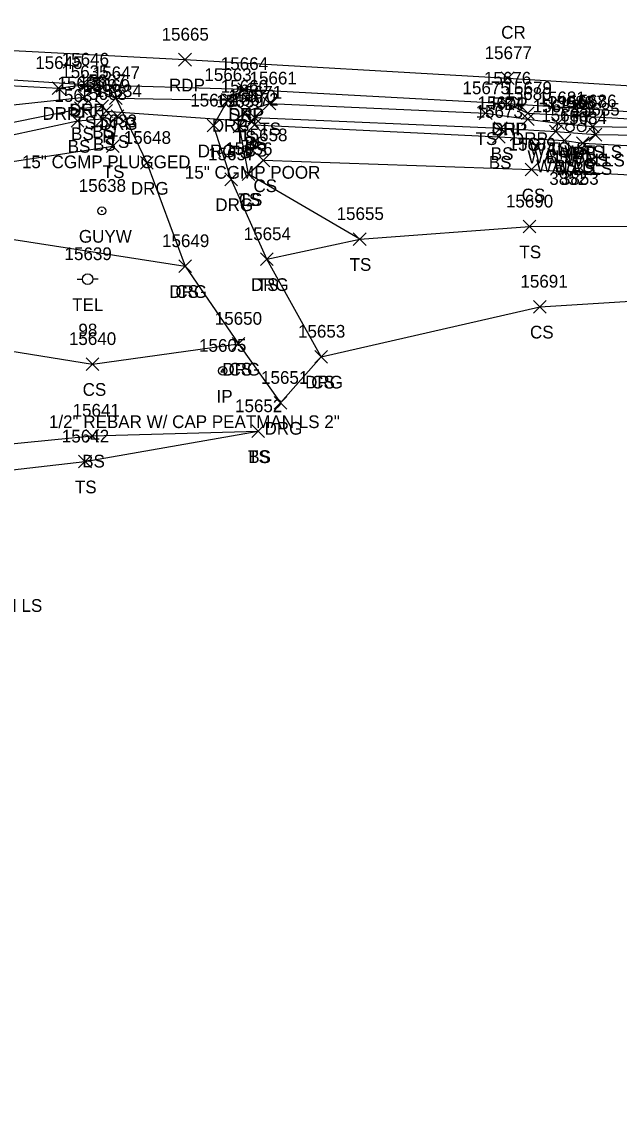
# Model space of a CAD drawing. Extents: x 1606530 to 1613020, y 784959 to 789666.
# Drawn here: x 1609492.8 to 1609586.7, y 788263.1 to 788433.6 of the extents above; entities that cross this region are included whole.
import ezdxf

# ---------------------------------------------------------------- set-up
doc = ezdxf.new("R2010")
doc.units = 0
for name, color, linetype in [('D_A', 7, 'Continuous'), ('D_C', 7, 'Continuous'), ('D_I', 7, 'Continuous'), ('D_TIC', 7, 'Continuous'), ('DCP', 7, 'Continuous'), ('L_A', 7, 'Continuous'), ('L_C', 7, 'Continuous'), ('L_I', 7, 'Continuous'), ('L_TIC', 7, 'Continuous'), ('LELB', 7, 'Continuous'), ('LMB', 7, 'Continuous'), ('LWS', 7, 'Continuous'), ('M_A', 7, 'Continuous'), ('M_C', 7, 'Continuous'), ('M_I', 7, 'Continuous'), ('MPIR', 7, 'Continuous'), ('P_A', 7, 'Continuous'), ('P_I', 7, 'Continuous'), ('P_TIC', 7, 'Continuous'), ('PET', 7, 'Continuous'), ('PSP', 7, 'Continuous'), ('R_A', 7, 'Continuous'), ('R_I', 7, 'Continuous'), ('R_TIC', 7, 'Continuous'), ('RDG', 7, 'Continuous'), ('RDP', 7, 'Continuous'), ('U_A', 7, 'Continuous'), ('U_C', 7, 'Continuous'), ('U_I', 7, 'Continuous'), ('UP', 7, 'Continuous'), ('UPGW', 7, 'Continuous')]:
    doc.layers.add(name, color=color, linetype=linetype)

msp = doc.modelspace()

# ---------------------------------------------------------------- linework, layer by layer
at = {"layer": 'D_TIC'}
for points in [[(1609505.07, 788418.52), (1609507.07, 788420.52)], [(1609507.07, 788418.52), (1609505.07, 788420.52)], [(1609528, 788416.87), (1609530, 788418.87)], [(1609530, 788416.87), (1609528, 788418.87)]]:
    msp.add_lwpolyline(points, dxfattribs=at)
at = {"layer": 'DCP'}
msp.add_lwpolyline([(1609506.07, 788419.52), (1609529, 788417.87)], dxfattribs=at)
at = {"layer": 'L_TIC'}
for points in [[(1609501.63, 788420.7), (1609503.63, 788422.7)], [(1609503.63, 788420.7), (1609501.63, 788422.7)], [(1609501.63, 788420.7), (1609503.63, 788422.7)], [(1609503.63, 788420.7), (1609501.63, 788422.7)], [(1609504.42, 788419.27), (1609506.42, 788421.27)], [(1609506.42, 788419.27), (1609504.42, 788421.27)], [(1609530.71, 788419.7), (1609532.71, 788421.7)], [(1609532.71, 788419.7), (1609530.71, 788421.7)], [(1609501.09, 788418.94), (1609503.09, 788420.94)], [(1609503.09, 788418.94), (1609501.09, 788420.94)], [(1609506.85, 788417.71), (1609508.85, 788419.71)], [(1609508.85, 788417.71), (1609506.85, 788419.71)], [(1609526.84, 788418.41), (1609528.84, 788420.41)], [(1609528.84, 788418.41), (1609526.84, 788420.41)], [(1609528.36, 788417.48), (1609530.36, 788419.48)], [(1609530.36, 788417.48), (1609528.36, 788419.48)], [(1609528.36, 788417.48), (1609530.36, 788419.48)], [(1609530.36, 788417.48), (1609528.36, 788419.48)], [(1609564.72, 788418.17), (1609566.72, 788420.17)], [(1609566.72, 788418.17), (1609564.72, 788420.17)], [(1609500.55, 788416.96), (1609502.55, 788418.96)], [(1609502.55, 788416.96), (1609500.55, 788418.96)], [(1609504.55, 788417.27), (1609506.55, 788419.27)], [(1609506.55, 788417.27), (1609504.55, 788419.27)], [(1609504.55, 788417.27), (1609506.55, 788419.27)], [(1609506.55, 788417.27), (1609504.55, 788419.27)], [(1609526.02, 788416.08), (1609528.02, 788418.08)], [(1609528.02, 788416.08), (1609526.02, 788418.08)], [(1609528.36, 788416.35), (1609530.36, 788418.35)], [(1609530.36, 788416.35), (1609528.36, 788418.35)], [(1609567.08, 788415.81), (1609569.08, 788417.81)], [(1609569.08, 788415.81), (1609567.08, 788417.81)], [(1609571.37, 788417.25), (1609573.37, 788419.25)], [(1609573.37, 788417.25), (1609571.37, 788419.25)], [(1609576.09, 788416.59), (1609578.09, 788418.59)], [(1609578.09, 788416.59), (1609576.09, 788418.59)], [(1609576.09, 788416.59), (1609578.09, 788418.59)], [(1609578.09, 788416.59), (1609576.09, 788418.59)], [(1609581.55, 788416.1), (1609583.55, 788418.1)], [(1609583.55, 788416.1), (1609581.55, 788418.1)], [(1609581.55, 788416.1), (1609583.55, 788418.1)], [(1609583.55, 788416.1), (1609581.55, 788418.1)], [(1609566.77, 788414.45), (1609568.77, 788416.45)], [(1609568.77, 788414.45), (1609566.77, 788416.45)], [(1609575.76, 788415.31), (1609577.76, 788417.31)], [(1609577.76, 788415.31), (1609575.76, 788417.31)], [(1609575.76, 788415.31), (1609577.76, 788417.31)], [(1609577.76, 788415.31), (1609575.76, 788417.31)], [(1609582, 788414.8), (1609584, 788416.8)], [(1609584, 788414.8), (1609582, 788416.8)], [(1609582, 788414.8), (1609584, 788416.8)], [(1609584, 788414.8), (1609582, 788416.8)], [(1609506.1, 788412.97), (1609508.1, 788414.97)], [(1609508.1, 788412.97), (1609506.1, 788414.97)], [(1609577.1, 788413.87), (1609579.1, 788415.87)], [(1609579.1, 788413.87), (1609577.1, 788415.87)], [(1609577.1, 788413.87), (1609579.1, 788415.87)], [(1609579.1, 788413.87), (1609577.1, 788415.87)], [(1609580, 788413.46), (1609582, 788415.46)], [(1609582, 788413.46), (1609580, 788415.46)], [(1609580, 788413.46), (1609582, 788415.46)], [(1609582, 788413.46), (1609580, 788415.46)], [(1609529.76, 788410.76), (1609531.76, 788412.76)], [(1609531.76, 788410.76), (1609529.76, 788412.76)], [(1609571.94, 788409.3), (1609573.94, 788411.3)], [(1609573.94, 788409.3), (1609571.94, 788411.3)], [(1609527.45, 788408.59), (1609529.45, 788410.59)], [(1609529.45, 788408.59), (1609527.45, 788410.59)], [(1609527.45, 788408.59), (1609529.45, 788410.59)], [(1609529.45, 788408.59), (1609527.45, 788410.59)], [(1609571.62, 788400.34), (1609573.62, 788402.34)], [(1609573.62, 788400.34), (1609571.62, 788402.34)], [(1609544.91, 788398.37), (1609546.91, 788400.37)], [(1609546.91, 788398.37), (1609544.91, 788400.37)], [(1609544.91, 788398.37), (1609546.91, 788400.37)], [(1609546.91, 788398.37), (1609544.91, 788400.37)], [(1609517.48, 788394.11), (1609519.48, 788396.11)], [(1609519.48, 788394.11), (1609517.48, 788396.11)], [(1609530.31, 788395.2), (1609532.31, 788397.2)], [(1609532.31, 788395.2), (1609530.31, 788397.2)], [(1609573.25, 788387.73), (1609575.25, 788389.73)], [(1609575.25, 788387.73), (1609573.25, 788389.73)], [(1609525.85, 788381.89), (1609527.85, 788383.89)], [(1609527.85, 788381.89), (1609525.85, 788383.89)], [(1609502.91, 788378.7), (1609504.91, 788380.7)], [(1609504.91, 788378.7), (1609502.91, 788380.7)], [(1609538.85, 788379.86), (1609540.85, 788381.86)], [(1609540.85, 788379.86), (1609538.85, 788381.86)], [(1609528.95, 788368.13), (1609530.95, 788370.13)], [(1609530.95, 788368.13), (1609528.95, 788370.13)], [(1609528.95, 788368.13), (1609530.95, 788370.13)], [(1609530.95, 788368.13), (1609528.95, 788370.13)], [(1609502.84, 788367.43), (1609504.84, 788369.43)], [(1609504.84, 788367.43), (1609502.84, 788369.43)], [(1609501.72, 788363.36), (1609503.72, 788365.36)], [(1609503.72, 788363.36), (1609501.72, 788365.36)]]:
    msp.add_lwpolyline(points, dxfattribs=at)
at = {"layer": 'LELB'}
for points in [[(1608830.7, 788263.06), (1608870.16, 788285.39), (1608903.61, 788303.66), (1608913.17, 788310.86), (1608944.69, 788327.51), (1608982.09, 788348.33), (1609025.65, 788367.84), (1609062.43, 788383.44), (1609080.36, 788388.45), (1609093.56, 788391.85), (1609111.49, 788398.34), (1609124.29, 788403.55), (1609165.33, 788413.89), (1609196.53, 788419.38), (1609241.91, 788424.94), (1609287.83, 788428.62), (1609331.16, 788428.8), (1609379, 788428.23), (1609424.69, 788425.72), (1609443.9, 788424.45), (1609475.84, 788418.57), (1609486.48, 788419.99), (1609502.63, 788421.7)], [(1609485.22, 788416.48), (1609502.09, 788419.94), (1609505.42, 788420.27), (1609505.55, 788418.27)], [(1609545.91, 788399.37), (1609528.45, 788409.59), (1609527.02, 788417.08), (1609527.84, 788419.41), (1609531.71, 788420.7), (1609565.72, 788419.17), (1609572.37, 788418.25), (1609577.09, 788417.59), (1609582.55, 788417.1), (1609600.8, 788416.78), (1609640.22, 788414.78), (1609644.48, 788414.01)], [(1609229.47, 788383.53), (1609235.87, 788391.77), (1609234.95, 788395.09), (1609256.53, 788397.81), (1609290, 788390.61), (1609315.27, 788387.55), (1609343.3, 788388.82), (1609351.97, 788404.1), (1609376.56, 788405.69), (1609392.36, 788394.13), (1609429.62, 788393.16), (1609442.68, 788388.57), (1609459.97, 788389.84), (1609474.42, 788390.35), (1609486.77, 788400.06), (1609484.73, 788410.56), (1609507.1, 788413.97), (1609507.85, 788418.71)], [(1609484.45, 788414.31), (1609501.55, 788417.96), (1609505.55, 788418.27)], [(1609529.36, 788418.48), (1609568.08, 788416.81), (1609576.76, 788416.31), (1609583, 788415.8), (1609600.83, 788415.56), (1609643.04, 788412.57), (1609654.17, 788408.61), (1609673.89, 788409.36), (1609681.93, 788408.64)], [(1609529.36, 788418.48), (1609529.36, 788417.35), (1609567.77, 788415.45), (1609578.1, 788414.87)], [(1609581, 788414.46), (1609600.81, 788413.42), (1609641.86, 788410.78), (1609654.08, 788402.78)], [(1609528.45, 788409.59), (1609530.76, 788411.76), (1609572.94, 788410.3), (1609601.01, 788408.82), (1609637.62, 788405.33), (1609649.17, 788399.51)], [(1609531.31, 788396.2), (1609545.91, 788399.37), (1609572.62, 788401.34), (1609601.06, 788401.39), (1609632.84, 788398.67), (1609642.01, 788393.11), (1609650.53, 788395.19), (1609670.09, 788397.81), (1609682.77, 788402.8)], [(1609486.77, 788400.06), (1609518.48, 788395.11)], [(1609474.42, 788390.35), (1609484.36, 788382.81), (1609503.91, 788379.7), (1609526.85, 788382.89)], [(1609539.85, 788380.86), (1609574.25, 788388.73), (1609601.06, 788390.36), (1609626.16, 788389.25), (1609636.41, 788387.85), (1609650.39, 788385.69)], [(1609374.03, 788361.62), (1609409.62, 788364.21), (1609429.2, 788364.13), (1609464.94, 788364.57), (1609503.84, 788368.43), (1609529.95, 788369.13)], [(1609382.71, 788349.03), (1609409.78, 788351.37), (1609431.66, 788354.24), (1609466.67, 788360.22), (1609502.72, 788364.36), (1609529.95, 788369.13)]]:
    msp.add_lwpolyline(points, dxfattribs=at)
at = {"layer": 'LMB'}
for p, q in [((1609579.63, 788419.5), (1609580.92, 788419.12)), ((1609579.63, 788416.91), (1609579.63, 788419.5)), ((1609581.45, 788419.52), (1609582.75, 788419.13)), ((1609581.46, 788416.92), (1609581.46, 788419.52)), ((1609579.63, 788418.6), (1609580.91, 788419.11)), ((1609581.46, 788418.62), (1609582.74, 788419.13)), ((1609578.98, 788416.9), (1609578.98, 788416.9)), ((1609580.8, 788416.92), (1609580.8, 788416.92))]:
    msp.add_line(p, q, dxfattribs=at)
for centre in [(1609578.98, 788416.9), (1609580.8, 788416.92)]:
    msp.add_circle(centre, 0.656, dxfattribs=at)
at = {"layer": 'LWS'}
msp.add_lwpolyline([(1609577.09, 788417.59), (1609576.76, 788416.31), (1609578.1, 788414.87), (1609581, 788414.46), (1609583, 788415.8), (1609582.55, 788417.1)], dxfattribs=at)
at = {"layer": 'MPIR'}
msp.add_lwpolyline([(1609524.37, 788378.96), (1609524.08, 788378.46), (1609524.66, 788378.46)], close=True, dxfattribs=at)
msp.add_circle((1609524.37, 788378.63), 0.667, dxfattribs=at)
at = {"layer": 'P_TIC'}
for points in [[(1609517.44, 788426.6), (1609519.44, 788428.6)], [(1609519.44, 788426.6), (1609517.44, 788428.6)], [(1609501.75, 788422.67), (1609503.75, 788424.67)], [(1609503.75, 788422.67), (1609501.75, 788424.67)], [(1609568.18, 788423.68), (1609570.18, 788425.68)], [(1609570.18, 788423.68), (1609568.18, 788425.68)], [(1609526.75, 788421.97), (1609528.75, 788423.97)], [(1609528.75, 788421.97), (1609526.75, 788423.97)], [(1609568.13, 788419.68), (1609570.13, 788421.68)], [(1609570.13, 788419.68), (1609568.13, 788421.68)]]:
    msp.add_lwpolyline(points, dxfattribs=at)
at = {"layer": 'PET'}
msp.add_lwpolyline([(1608827.2, 788266.24), (1608867.86, 788290.54), (1608906.68, 788312.86), (1608942.68, 788332.75), (1608980.54, 788352.16), (1609023.57, 788373.22), (1609061.44, 788389.9), (1609090.8, 788401.17), (1609121.92, 788410.09), (1609165.17, 788420), (1609195.85, 788425.54), (1609240.14, 788431.13), (1609287.88, 788434.37), (1609331.48, 788435.11), (1609378.89, 788434.05), (1609425.43, 788432.25), (1609443.83, 788431.33), (1609477.32, 788429.78), (1609518.44, 788427.6), (1609569.18, 788424.68), (1609602.99, 788422.58), (1609641.45, 788420.37), (1609681.7, 788417.92), (1609727.38, 788415.53)], dxfattribs=at)
at = {"layer": 'PSP'}
msp.add_lwpolyline([(1609378.92, 788430.28), (1609425.01, 788428.31), (1609443, 788427.34), (1609476.79, 788425.47), (1609487.21, 788424.7), (1609502.75, 788423.67), (1609527.75, 788422.97), (1609569.13, 788420.68), (1609592.88, 788419.12), (1609602.1, 788418.65), (1609640.72, 788416.23), (1609676.37, 788413.47), (1609681.63, 788413.32), (1609727.4, 788411.58)], dxfattribs=at)
at = {"layer": 'R_TIC'}
for points in [[(1609501.75, 788422.67), (1609503.75, 788424.67)], [(1609503.75, 788422.67), (1609501.75, 788424.67)], [(1609501.75, 788422.67), (1609503.75, 788424.67)], [(1609503.75, 788422.67), (1609501.75, 788424.67)], [(1609497.54, 788422.13), (1609499.54, 788424.13)], [(1609499.54, 788422.13), (1609497.54, 788424.13)], [(1609526.75, 788421.97), (1609528.75, 788423.97)], [(1609528.75, 788421.97), (1609526.75, 788423.97)], [(1609506.57, 788420.54), (1609508.57, 788422.54)], [(1609508.57, 788420.54), (1609506.57, 788422.54)], [(1609506.57, 788420.54), (1609508.57, 788422.54)], [(1609508.57, 788420.54), (1609506.57, 788422.54)], [(1609524.18, 788420.25), (1609526.18, 788422.25)], [(1609526.18, 788420.25), (1609524.18, 788422.25)], [(1609524.18, 788420.25), (1609526.18, 788422.25)], [(1609526.18, 788420.25), (1609524.18, 788422.25)], [(1609568.13, 788419.68), (1609570.13, 788421.68)], [(1609570.13, 788419.68), (1609568.13, 788421.68)], [(1609571.35, 788418.16), (1609573.35, 788420.16)], [(1609573.35, 788418.16), (1609571.35, 788420.16)], [(1609521.95, 788416.23), (1609523.95, 788418.23)], [(1609523.95, 788416.23), (1609521.95, 788418.23)], [(1609511.45, 788410.35), (1609513.45, 788412.35)], [(1609513.45, 788410.35), (1609511.45, 788412.35)], [(1609524.72, 788407.77), (1609526.72, 788409.77)], [(1609526.72, 788407.77), (1609524.72, 788409.77)], [(1609517.48, 788394.11), (1609519.48, 788396.11)], [(1609519.48, 788394.11), (1609517.48, 788396.11)], [(1609530.31, 788395.2), (1609532.31, 788397.2)], [(1609532.31, 788395.2), (1609530.31, 788397.2)], [(1609525.85, 788381.89), (1609527.85, 788383.89)], [(1609527.85, 788381.89), (1609525.85, 788383.89)], [(1609538.85, 788379.86), (1609540.85, 788381.86)], [(1609540.85, 788379.86), (1609538.85, 788381.86)], [(1609532.47, 788372.59), (1609534.47, 788374.59)], [(1609534.47, 788372.59), (1609532.47, 788374.59)]]:
    msp.add_lwpolyline(points, dxfattribs=at)
at = {"layer": 'RDG'}
msp.add_lwpolyline([(1609507.57, 788421.54), (1609512.45, 788411.35), (1609518.48, 788395.11), (1609526.85, 788382.89), (1609533.47, 788373.59), (1609539.85, 788380.86), (1609531.31, 788396.2), (1609525.72, 788408.77), (1609522.95, 788417.23), (1609525.18, 788421.25)], dxfattribs=at)
at = {"layer": 'RDP'}
for points in [[(1609487.21, 788424.7), (1609488.81, 788423.66), (1609498.54, 788423.13), (1609502.75, 788423.67)], [(1609502.75, 788423.67), (1609507.57, 788421.54), (1609525.18, 788421.25), (1609527.75, 788422.97)], [(1609569.13, 788420.68), (1609572.35, 788419.16), (1609590.27, 788418.17), (1609592.88, 788419.12)]]:
    msp.add_lwpolyline(points, dxfattribs=at)
at = {"layer": 'UP'}
for p, q in [((1609501.48, 788393.06), (1609502.31, 788393.06)), ((1609503.14, 788393.06), (1609503.14, 788393.06)), ((1609504.81, 788393.06), (1609503.98, 788393.06)), ((1609503.98, 788393.06), (1609503.98, 788393.06)), ((1609504.81, 788393.06), (1609504.81, 788393.06))]:
    msp.add_line(p, q, dxfattribs=at)
msp.add_circle((1609503.14, 788393.06), 0.833, dxfattribs=at)
at = {"layer": 'UPGW'}
for radius in [0.625, 0.0833]:
    msp.add_circle((1609505.37, 788403.8), radius, dxfattribs=at)

# ---------------------------------------------------------------- texts
at = {"layer": 'D_A'}
for p in [(1609505.45, 788414.52), (1609528.37, 788412.87)]:
    msp.add_text('P', height=2, dxfattribs=at).set_placement(p)
at = {"layer": 'D_C'}
for s, p in [('15" CGMP PLUGGED', (1609492.8, 788410.52)), ('15" CGMP POOR', (1609518.42, 788408.87))]:
    msp.add_text(s, height=2, dxfattribs=at).set_placement(p)
at = {"layer": 'D_I'}
for s, p in [('15669', (1609502.38, 788422.52)), ('15670', (1609525.27, 788420.87))]:
    msp.add_text(s, height=2, dxfattribs=at).set_placement(p)
at = {"layer": 'L_A'}
for s, p in [('TS', (1609501.04, 788416.7)), ('TS', (1609501.04, 788416.7)), ('BS', (1609500.53, 788414.94)), ('BS', (1609503.86, 788415.27)), ('TS', (1609526.25, 788414.41)), ('TS', (1609530.12, 788415.7)), ('TS', (1609564.13, 788414.17)), ('BS', (1609500, 788412.96)), ('BS', (1609503.99, 788413.27)), ('BS', (1609503.99, 788413.27)), ('TS', (1609506.26, 788413.71)), ('BS', (1609527.8, 788413.48)), ('BS', (1609527.8, 788413.48)), ('BS', (1609527.81, 788412.35)), ('TS', (1609570.78, 788413.25)), ('WALLS', (1609572.63, 788412.59)), ('TS', (1609575.5, 788412.59)), ('TS', (1609525.43, 788412.08)), ('BS', (1609566.52, 788411.81)), ('WALLS', (1609572.3, 788411.31)), ('BS', (1609575.2, 788411.31)), ('MB', (1609577.28, 788411.9)), ('WALLS', (1609578.1, 788412.1)), ('WALLS', (1609578.54, 788410.8)), ('MB', (1609579.11, 788411.92)), ('TS', (1609580.96, 788412.1)), ('BS', (1609581.44, 788410.8)), ('TS', (1609505.51, 788408.97)), ('BS', (1609566.21, 788410.45)), ('WALLS', (1609573.65, 788409.87)), ('WALLS', (1609576.54, 788409.46)), ('BS', (1609576.54, 788409.87)), ('BS', (1609579.44, 788409.46)), ('CS', (1609529.2, 788406.76)), ('TS', (1609526.86, 788404.59)), ('CS', (1609526.89, 788404.59)), ('CS', (1609571.38, 788405.3)), ('TS', (1609571.03, 788396.34)), ('TS', (1609544.32, 788394.37)), ('TS', (1609544.32, 788394.37)), ('TS', (1609529.72, 788391.2)), ('CS', (1609516.92, 788390.11)), ('CS', (1609572.69, 788383.73)), ('CS', (1609525.29, 788377.89)), ('CS', (1609538.29, 788375.86)), ('CS', (1609502.35, 788374.7)), ('BS', (1609502.28, 788363.43)), ('TS', (1609528.36, 788364.13)), ('BS', (1609528.39, 788364.13)), ('TS', (1609501.13, 788359.36))]:
    msp.add_text(s, height=2, dxfattribs=at).set_placement(p)
at = {"layer": 'L_C'}
for s, p in [('3852', (1609575.72, 788407.9)), ('3853', (1609577.54, 788407.92))]:
    msp.add_text(s, height=2, dxfattribs=at).set_placement(p)
at = {"layer": 'L_I'}
for s, p in [('15635', (1609498.99, 788424.7)), ('15635', (1609498.99, 788424.7)), ('15636', (1609498.4, 788422.94)), ('15667', (1609501.73, 788423.27)), ('15661', (1609528.59, 788423.7)), ('15637', (1609497.92, 788420.96)), ('15668', (1609501.87, 788421.27)), ('15668', (1609501.87, 788421.27)), ('15634', (1609504.22, 788421.71)), ('15660', (1609524.07, 788422.41)), ('15671', (1609526.29, 788421.48)), ('15671', (1609526.29, 788421.48)), ('15675', (1609562.08, 788422.17)), ('15680', (1609568.65, 788421.25)), ('15659', (1609523.37, 788420.08)), ('15672', (1609525.73, 788420.35)), ('15674', (1609564.44, 788419.81)), ('15682', (1609573.12, 788419.31)), ('15682', (1609573.12, 788419.31)), ('15681', (1609574.02, 788420.59)), ('15681', (1609574.02, 788420.59)), ('15688', (1609575.34, 788419.9)), ('15687', (1609577.17, 788419.92)), ('15686', (1609578.86, 788420.1)), ('15686', (1609578.86, 788420.1)), ('15673', (1609564.13, 788418.45)), ('15683', (1609574.46, 788417.87)), ('15683', (1609574.46, 788417.87)), ('15684', (1609577.36, 788417.46)), ('15684', (1609577.36, 788417.46)), ('15685', (1609579.36, 788418.8)), ('15685', (1609579.36, 788418.8)), ('15633', (1609503.46, 788416.97)), ('15658', (1609527.12, 788414.76)), ('15656', (1609524.76, 788412.59)), ('15656', (1609524.76, 788412.59)), ('15689', (1609569.3, 788413.3)), ('15690', (1609568.9, 788404.34)), ('15655', (1609542.28, 788402.37)), ('15655', (1609542.28, 788402.37)), ('15654', (1609527.67, 788399.2)), ('15649', (1609514.83, 788398.11)), ('15691', (1609571.18, 788391.73)), ('15650', (1609523.12, 788385.89)), ('15653', (1609536.21, 788383.86)), ('15640', (1609500.19, 788382.7)), ('15641', (1609500.77, 788371.43)), ('15652', (1609526.31, 788372.13)), ('15652', (1609526.31, 788372.13)), ('15642', (1609499.08, 788367.36))]:
    msp.add_text(s, height=2, dxfattribs=at).set_placement(p)
at = {"layer": 'M_A'}
msp.add_text('IP', height=2, dxfattribs=at).set_placement((1609523.41, 788373.63))
at = {"layer": 'M_C'}
for s, p in [('1/2" REBAR W/ CAP PEATMAN LS 2"', (1609497.04, 788369.63)), ('1/2" REBAR W/ CAP PEATMAN LS', (1609453.44, 788340.71))]:
    msp.add_text(s, height=2, dxfattribs=at).set_placement(p)
at = {"layer": 'M_I'}
msp.add_text('15605', height=2, dxfattribs=at).set_placement((1609520.65, 788381.63))
at = {"layer": 'P_A'}
for s, p in [('CR', (1609568.16, 788430.9)), ('RDP', (1609515.93, 788422.6)), ('RDP', (1609566.67, 788419.68)), ('SHP', (1609500.29, 788418.67)), ('SHP', (1609525.29, 788417.97)), ('SHP', (1609566.67, 788415.68))]:
    msp.add_text(s, height=2, dxfattribs=at).set_placement(p)
at = {"layer": 'P_I'}
for s, p in [('15665', (1609514.76, 788430.6)), ('15677', (1609565.55, 788427.68)), ('15646', (1609499.06, 788426.67)), ('15664', (1609524.07, 788425.97)), ('15676', (1609565.44, 788423.68))]:
    msp.add_text(s, height=2, dxfattribs=at).set_placement(p)
at = {"layer": 'R_A'}
for s, p in [('DRP', (1609496.03, 788418.13)), ('DRP', (1609500.24, 788418.67)), ('DRP', (1609500.24, 788418.67)), ('DRP', (1609525.24, 788417.97)), ('DRG', (1609505.06, 788416.54)), ('DRP', (1609505.06, 788416.54)), ('DRG', (1609522.66, 788416.25)), ('DRP', (1609522.66, 788416.25)), ('DRP', (1609566.62, 788415.68)), ('DRP', (1609569.84, 788414.16)), ('DRG', (1609520.44, 788412.23)), ('DRG', (1609509.93, 788406.35)), ('DRG', (1609523.21, 788403.77)), ('DRG', (1609528.8, 788391.2)), ('DRG', (1609515.97, 788390.11)), ('DRG', (1609524.33, 788377.89)), ('DRG', (1609537.33, 788375.86)), ('DRG', (1609530.95, 788368.59))]:
    msp.add_text(s, height=2, dxfattribs=at).set_placement(p)
at = {"layer": 'R_I'}
for s, p in [('15645', (1609494.9, 788426.13)), ('15646', (1609499.06, 788426.67)), ('15646', (1609499.06, 788426.67)), ('15664', (1609524.07, 788425.97)), ('15647', (1609503.93, 788424.54)), ('15647', (1609503.93, 788424.54)), ('15663', (1609521.49, 788424.25)), ('15663', (1609521.49, 788424.25)), ('15676', (1609565.44, 788423.68)), ('15679', (1609568.7, 788422.16)), ('15662', (1609519.27, 788420.23)), ('15648', (1609508.81, 788414.35)), ('15657', (1609522.08, 788411.77)), ('15654', (1609527.67, 788399.2)), ('15649', (1609514.83, 788398.11)), ('15650', (1609523.12, 788385.89)), ('15653', (1609536.21, 788383.86)), ('15651', (1609530.4, 788376.59))]:
    msp.add_text(s, height=2, dxfattribs=at).set_placement(p)
at = {"layer": 'U_A'}
for s, p in [('GUYW', (1609501.76, 788398.8)), ('TEL', (1609500.7, 788388.06))]:
    msp.add_text(s, height=2, dxfattribs=at).set_placement(p)
at = {"layer": 'U_C'}
msp.add_text('98', height=2, dxfattribs=at).set_placement((1609501.68, 788384.06))
at = {"layer": 'U_I'}
for s, p in [('15638', (1609501.73, 788406.8)), ('15639', (1609499.5, 788396.06))]:
    msp.add_text(s, height=2, dxfattribs=at).set_placement(p)

doc.saveas('drawing.dxf')
